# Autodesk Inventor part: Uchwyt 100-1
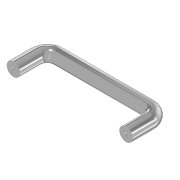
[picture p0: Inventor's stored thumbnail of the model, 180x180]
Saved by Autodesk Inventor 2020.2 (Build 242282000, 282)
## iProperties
Created: 2005-10
Part Number: Uchwyt 100-1
Document SubType Name: Modeling
Designer: F.Stasiak
Density: 1 g/cm^3
Material: Ogólny
Appearance: Chrom — polerowany
Manager: www.cadconsulting.pl
Company: Fabian Stasiak CAD Consulting
Author: F.Stasiak
Subject: Zbiór ćwiczeń. Autodesk Inventor 2020. Kurs podstawowy
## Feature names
1. Przeciągnięcie1
2. Otwór1 [Hole]
## Parameters: d3 = 12 mm, d4 = 0, d5 = 3 mm, d6 = 6 mm, d7 = 4 mm, d8 = 2 mm, d9 = 90 deg, d10 = 8 mm, d11 = 118 deg, d14 = 0, d15 = 0, d16 = 0
